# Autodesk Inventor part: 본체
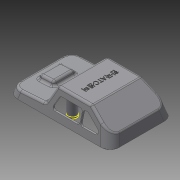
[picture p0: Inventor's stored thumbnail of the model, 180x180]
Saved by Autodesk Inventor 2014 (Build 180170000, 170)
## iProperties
Created: 2015-05
Part Number: 본체
Material: Generic
Document SubType Name: Modeling
Designer: Administrator
Density: 1 g/cm^3
Appearance: Default
Author: Administrator
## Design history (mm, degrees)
sketch "스케치4"
  geometry: L1 (61, 0)-(-61, 0); L2 (-61, 0)-(-57.738, 12.175); L3 (-57.738, 12.175)-(-31, 30); L4 (-31, 30)-(9.684, 30); L5 (19, 10.201)-(58.826, 8.114); L6 (58.826, 8.114)-(61, 0); L7 (-57.738, 12.175)-(-61, 10); L8 (-61, 0)-(-61, 10); L9 (61, 0)-(61, 8); L10 (58.826, 8.114)-(61, 8); L11 (19, 10.201)-(9.684, 30); 2 further points
  constraints: 22 end point, 2 collinear, 2 parallel, 1 coincident, 1 horizontal, 1 midpoint, 1 perpendicular
  dimensions: "d35" = 122 distance of L1.start L1.end; "d36" = 8 distance of L1.start L9.end; "d37" = 3 deg angle of L1 L5; "d38" = 105 deg angle of L1 L6; "d39" = 30 distance between parallel lines of L1 L4; "d40" = 20 vertical distance of L7.end L3.end; "d41" = 30 horizontal distance of L3.end L7.end; "d42" = 105 deg angle of L1 L2; "d46" = 42 horizontal distance of L5.start L1.start
extrude "돌출1" new body sketch "스케치4" stored distance "d44" = 76; taper "d45" = 0 deg
sketch "스케치5"
  geometry: L1 (19, 10.201)-(58.826, 8.114) reference; L2 (50.015, 8.576)-(48.459, 13.664); L3 (48.459, 13.664)-(32.122, 14.52); L4 (32.122, 14.52)-(30.042, 9.622); L5 (58.826, 8.114)-(61, 8); L6 (61, 0)-(58.826, 8.114) reference; L7 (61, 0)-(61, 8); 1 further point
  constraints: 10 end point, 2 parallel, 2 point on line, 1 vertical
  dimensions: "d47" = 11 distance of L5.end L2.start; "d48" = 20 distance of L2.start L4.end; "d49" = 5 distance between parallel lines of L1 L3; "d50" = 70 deg angle of L1 L4; "d51" = 70 deg angle of L1 L2
extrude "돌출2" join sketch "스케치5" stored distance "d52" = 26; taper "d53" = 0 deg
fillet "모깎기1" dims "d54" = 3
fillet "모깎기2" dims "d55" = 3
node "작업 평면1"
sketch "스케치6"
  geometry: L1 (0, 0)-(-76, 0) reference; L2 (0, 0)-(-8.038, 30); L3 (-76, 0)-(-67.962, 30); L4 (-76, 10.201)-(-76, 30) reference; L5 (-76, 30)-(0, 30) reference; L6 (0, 30)-(0, 10.201) reference; L7 (-67.962, 30)-(-76, 30); L8 (-8.038, 30)-(0, 30); L9 (0, 0)-(0, 30); L10 (-76, 0)-(-76, 30); 1 further point
  constraints: 12 end point, 4 collinear, 2 point on line
  dimensions: "d56" = 105 deg angle of L1 L3; "d57" = 105 deg angle of L1 L2
extrude "돌출3" cut sketch "스케치6" stored distance "d58" = 26; taper "d59" = 0 deg
fillet "모깎기3" dims "d60" = 12
fillet "모깎기4" dims "d61" = 3
node "작업 평면2"
sketch "스케치7"
  geometry: A1 r 4 centre (5.409, 0) between (9.409, 0) and (1.409, 0); A2 r 4 centre (16.409, 0) between (20.409, 0) and (12.409, 0); A3 r 4 centre (36.409, 0) between (40.409, 0) and (32.409, 0); A4 r 4 centre (47.409, 0) between (51.409, 0) and (43.409, 0); 9 further points
  constraints: 8 point on circle, 5 horizontal alignment, 4 centre point, 15 other
  dimensions: "d62" = 8 diameter of A1; "d63" = 8 diameter of A2; "d64" = 8 diameter of A3; "d66" = 10 distance of A2.centre point (26.409, 0); "d67" = 11 distance of A1.centre A2.centre; "d68" = 10 distance of point (26.409, 0) A3.centre; "d69" = 11 distance of A3.centre A4.centre; "d70" = 8 diameter of A4
extrude "돌출4" join sketch "스케치7" stored distance "d71" = 26; taper "d72" = 0 deg
sketch "스케치8"
  geometry: L1 (0, -9.409)-(0, -1.409) reference; L2 (0, -20.409)-(0, -12.409) reference; L3 (0, -40.409)-(0, -32.409) reference; L4 (0, -51.409)-(0, -43.409) reference; L5 (0, -51.409)-(0, -43.409) reference; A1 r 4 centre (0, -5.409) between (0, -9.409) and (0, -1.409) reference; A2 r 4 centre (0, -16.409) between (0, -20.409) and (0, -12.409) reference; A3 r 4 centre (0, -36.409) between (0, -40.409) and (0, -32.409) reference; A4 r 4 centre (0, -47.409) between (0, -51.409) and (0, -43.409) reference; 1 further point
extrude "돌출5" join sketch "스케치8" distance "d73" = 2; taper "d74" = 0 deg
chamfer "모따기1" distance "d75" = 1; stored, may be unused: second distance "d76" = 2, angle "d77" = 45 deg
feature "쉘1" dims "d78" = 2
sketch "스케치9"
  geometry: L1 (68.78, -1.251)-(68.78, -54.068) reference; 2 further points
  constraints: 1 horizontal alignment, 1 other
  dimensions: "d79" = 50 distance from line of L1 point (18.78, -27.66)
feature "엠보싱1" sketch "스케치9" dims "d48" = 20, "d80" = 0.5, "d81" = 0
node "작업 평면3"
sketch "스케치11"
  geometry: L1 (-15.521, 11.325)-(-7.78, 27.776) reference; L2 (-7.78, 27.776)-(30.092, 27.776) reference; L3 (30.092, 27.776)-(44.549, 18.138) reference; L4 (44.549, 18.138)-(49.409, 0) reference; L5 (-5.418, 21.054)-(-9.652, 12.054); L6 (-6.938, 7.776)-(19.335, 7.776); L7 (22.335, 10.776)-(22.335, 19.776); L8 (19.335, 22.776)-(-2.703, 22.776); L9 (26.078, 22.776)-(27.669, 22.776); L10 (29.334, 22.273)-(42.834, 13.273); L11 (41.169, 7.776)-(26.078, 7.776); L12 (23.078, 10.776)-(23.078, 19.776); A1 r 6 centre (-20.95, 13.88) between (-20.636, 7.888) and (-15.521, 11.325) reference; A2 r 3 centre (-6.938, 10.776) between (-9.652, 12.054) and (-6.938, 7.776); A3 r 3 centre (-2.703, 19.776) between (-2.703, 22.776) and (-5.418, 21.054); A4 r 3 centre (19.335, 19.776) between (22.335, 19.776) and (19.335, 22.776); A5 r 3 centre (19.335, 10.776) between (19.335, 7.776) and (22.335, 10.776); A6 r 3 centre (26.078, 10.776) between (23.078, 10.776) and (26.078, 7.776); A7 r 3 centre (26.078, 19.776) between (26.078, 22.776) and (23.078, 19.776); A8 r 3 centre (27.669, 19.776) between (29.334, 22.273) and (27.669, 22.776); A9 r 3 centre (41.169, 10.776) between (41.169, 7.776) and (42.834, 13.273); 3 further points
  constraints: 16 end point, 16 point on circle, 16 tangent, 8 centre point, 7 equal radius, 4 parallel, 4 point on line, 3 perpendicular, 1 collinear
  dimensions: "d83" = 5 distance between parallel lines of L2 L8; "d84" = 5 distance between parallel lines of L2 L9; "d85" = 5 distance between parallel lines of L10 L3; "d86" = 5 distance between parallel lines of L1 L5; "d87" = 34 distance from line of point (-11.665, 7.776) L7; "d88" = 15 distance between parallel lines of L11 L9; "d89" = 15 distance between parallel lines of L6 L8; "d90" = 28 distance from line of L12 point (51.078, 7.776); "d91" = 3 radius of A2
extrude "돌출6" cut sketch "스케치11" stored distance "d92" = 10; taper "d93" = 0 deg
sketch "스케치12"
  geometry: L1 (98.679, -73.929)-(0.139, -73.929) reference; L2 (-9.521, -64.27)-(-9.521, -11.73) reference; L3 (0.139, -2.071)-(98.679, -2.071) reference; L4 (108.338, -11.73)-(108.338, -15) reference; L5 (108.338, -15)-(110.409, -15) reference; L6 (110.409, -15)-(110.409, -19) reference; L7 (110.409, -19)-(108.338, -19) reference; L8 (108.338, -19)-(108.338, -26) reference; L9 (108.338, -26)-(110.409, -26) reference; L10 (110.409, -26)-(110.409, -30) reference; L11 (110.409, -30)-(108.338, -30) reference; L12 (108.338, -30)-(108.338, -46) reference; L13 (108.338, -46)-(110.409, -46) reference; L14 (110.409, -46)-(110.409, -50) reference; L15 (110.409, -50)-(108.338, -50) reference; L16 (108.338, -50)-(108.338, -57) reference; L17 (108.338, -57)-(110.409, -57) reference; L18 (110.409, -57)-(110.409, -61) reference; L19 (110.409, -61)-(108.338, -61) reference; L20 (108.338, -61)-(108.338, -64.27) reference; L21 (0, 0)-(98.818, 0) reference; L22 (98.679, -1)-(0.139, -1); L23 (-10.591, -11.73)-(-10.591, -64.27); L24 (0.139, -75)-(98.679, -75); L25 (109.409, -64.27)-(109.409, -62.071); L26 (109.409, -62.071)-(111.479, -62.071); L27 (111.479, -62.071)-(111.479, -55.929); L28 (111.479, -55.929)-(109.409, -55.929); L29 (109.409, -55.929)-(109.409, -51.071); L30 (109.409, -51.071)-(111.479, -51.071); L31 (111.479, -51.071)-(111.479, -44.929); L32 (111.479, -44.929)-(109.409, -44.929); L33 (109.409, -44.929)-(109.409, -31.071); L34 (109.409, -31.071)-(111.479, -31.071); L35 (111.479, -31.071)-(111.479, -24.929); L36 (111.479, -24.929)-(109.409, -24.929); L37 (109.409, -24.929)-(109.409, -20.071); L38 (109.409, -20.071)-(111.479, -20.071); L39 (111.479, -20.071)-(111.479, -13.929); L40 (111.479, -13.929)-(109.409, -13.929); L41 (109.409, -13.929)-(109.409, -11.73); 5 further points; 4 other entities
  constraints: 40 end point, 7 parallel, 32 other
  dimensions: "d94" = 1 distance between parallel lines of L21 L22
extrude "돌출7" join sketch "스케치12" distance "d95" = 1; taper "d96" = 0 deg
sketch "스케치14"
  geometry: C1 r 5 at (-40, 0); C2 r 5 at (0, -22); C3 r 5 at (0, 22); C4 r 5 at (40, 0); 1 further point
  constraints: 4 centre point, 2 horizontal alignment, 2 vertical alignment
  dimensions: "d97" = 10 diameter of C1; "d98" = 10 diameter of C2; "d99" = 10 diameter of C3; "d100" = 10 diameter of C4; "d101" = 40 horizontal distance of C3.centre C1.centre; "d102" = 40 distance of point (0, 0) C4.centre; "d103" = 22 distance of point (0, 0) C3.centre; "d104" = 22 distance of point (0, 0) C2.centre
extrude "돌출8" join sketch "스케치14" stored distance "d105" = 1; taper "d106" = 0 deg
node "작업 평면4"
sketch "스케치16"
  geometry: L1 (-5, 0)-(5, 0) reference; L2 (5, 28)-(-5, 28) reference; L3 (5, 0)-(5, 28) reference; L4 (-5, 0)-(-5, 28) reference; 1 further point
  node "투영된 루프4"
sketch "스케치17"
  geometry: C1 r 5 at (0, 0) reference; C2 r 5 at (-40, 22) reference; C3 r 5 at (0, 44) reference; C4 r 5 at (40, 22) reference; 1 further point
  node "투영된 루프5"
  node "투영된 루프6"
  node "투영된 루프7"
node "작업 평면5"
sketch "스케치18"
  geometry: C1 r 5 at (0, -22) reference; C2 r 5 at (0, 22) reference; C3 r 5 at (-40, 0) reference; C4 r 5 at (40, 0) reference; 4 further points
  constraints: 4 coincident
  node "투영된 루프8"
  node "투영된 루프9"
  node "투영된 루프10"
  node "투영된 루프11"
node "솔리드1"
node "투영된 루프1"
node "투영된 루프2"
node "투영된 루프3"
other parameters: "d82" = -38, "d107" = -22, "d108" = 2
